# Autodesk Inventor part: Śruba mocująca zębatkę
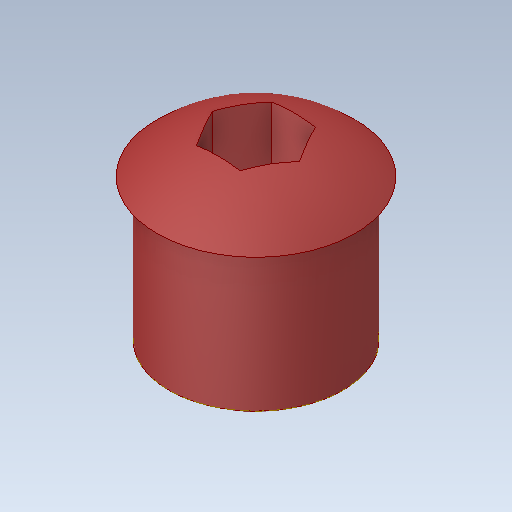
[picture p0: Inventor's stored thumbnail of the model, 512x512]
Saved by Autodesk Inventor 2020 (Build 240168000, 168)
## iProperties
Created: 2017-10
Part Number: Śruba mocująca zębatkę
Material: Ogólny
Document SubType Name: Modeling
Designer: Tomasz
Density: 1 g/cm^3
Appearance: Domyślna
Sending System: SolidWorks 2017
Last Author: Tomasz
Last Saved: 2017-10-01
Author: Tomasz
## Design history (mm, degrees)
feature "Extrude3"
feature "Surface-Imported1"
feature "Surface-Imported2"
node "Bryła1"
body "Srf1"
body "Srf2"
